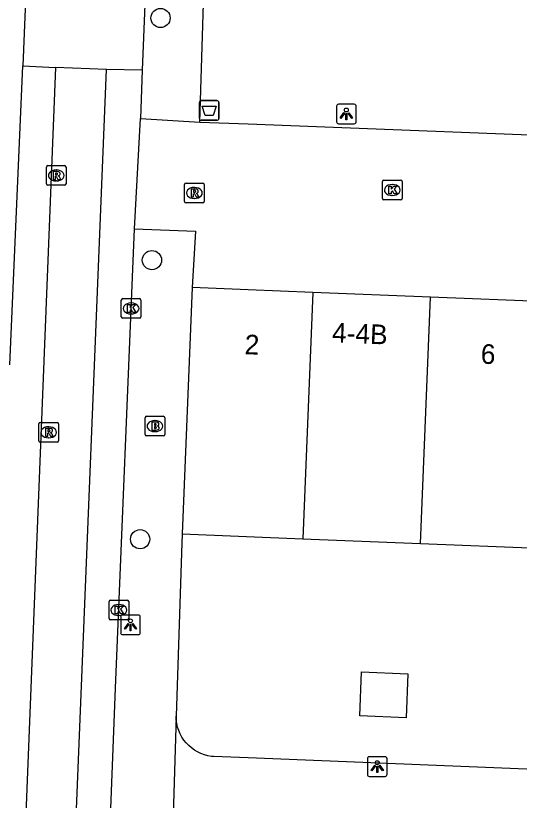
# Model space of a CAD drawing. Extents: x 160787 to 161428, y 386828 to 387483.
# Drawn here: x 160988.17 to 161013.79, y 387050.35 to 387090.27 of the extents above; entities that cross this region are included whole.
import ezdxf

# ---------------------------------------------------------------- set-up
doc = ezdxf.new("R2010")
doc.units = 0
for name, color, linetype in [('IMGEO_Afvalbak', 7, 'Continuous'), ('IMGEO_Boom', 7, 'Continuous'), ('IMGEO_Brandkraan', 7, 'Continuous'), ('IMGEO_Kolk', 7, 'Continuous'), ('IMGEO_Lichtpunt', 7, 'Continuous'), ('IMGEO_Pand', 7, 'Continuous'), ('IMGEO_Pand_nummerreeks', 7, 'Continuous'), ('IMGEO_Rijbaan_lokaal_gesloten', 7, 'Continuous'), ('IMGEO_Rijbaan_lokaal_open', 7, 'Continuous'), ('IMGEO_Rioolput', 7, 'Continuous'), ('IMGEO_Voetpad_open', 7, 'Continuous')]:
    doc.layers.add(name, color=color, linetype=linetype)

msp = doc.modelspace()

# ---------------------------------------------------------------- linework, layer by layer
at = {"layer": 'IMGEO_Afvalbak'}
for p, q in [((160997.617, 387085.95), (160998.407, 387085.95)), ((160998.407, 387085.95), (160997.617, 387085.95)), ((160997.517, 387085.05), (160997.517, 387085.85)), ((160997.517, 387085.85), (160997.517, 387085.05)), ((160998.507, 387085.85), (160998.507, 387085.05)), ((160998.507, 387085.05), (160998.507, 387085.85)), ((160998.407, 387084.95), (160997.617, 387084.95)), ((160997.617, 387084.95), (160998.407, 387084.95))]:
    msp.add_line(p, q, dxfattribs=at)
msp.add_lwpolyline([(160997.66, 387085.664), (160998.364, 387085.664), (160998.215, 387085.194), (160997.809, 387085.194), (160997.66, 387085.664)], dxfattribs=at)
for centre, start, end in [((160997.617, 387085.85), 90, 180), ((160997.617, 387085.85), 90, 180), ((160998.407, 387085.85), 0, 90), ((160998.407, 387085.85), 360, 90), ((160997.617, 387085.05), 180, 270), ((160997.617, 387085.05), 180, 270), ((160998.407, 387085.05), 270, 0), ((160998.407, 387085.05), 270, 0)]:
    msp.add_arc(centre, 0.1, start, end, dxfattribs=at)
at = {"layer": 'IMGEO_Boom'}
for centre in [(160995.542, 387090.155), (160995.105, 387077.836), (160994.503, 387063.636)]:
    msp.add_circle(centre, 0.489, dxfattribs=at)
at = {"layer": 'IMGEO_Brandkraan'}
for p, q in [((160994.757, 387068.964), (160994.757, 387069.816)), ((160994.832, 387069.89), (160995.684, 387069.89)), ((160995.245, 387069.67), (160995.27, 387069.67)), ((160995.758, 387069.816), (160995.758, 387068.964)), ((160995.684, 387068.89), (160994.832, 387068.89)), ((160995.268, 387069.11), (160995.243, 387069.11))]:
    msp.add_line(p, q, dxfattribs=at)
for points in [[(160994.757, 387068.964), (160994.757, 387069.816)], [(160994.832, 387069.89), (160995.684, 387069.89)], [(160995.105, 387069.59), (160995.105, 387069.19), (160995.318, 387069.19)], [(160995.336, 387069.59), (160995.105, 387069.59)], [(160995.758, 387069.816), (160995.758, 387068.964)], [(160995.284, 387069.509), (160995.23, 387069.509), (160995.23, 387069.433)], [(160995.23, 387069.433), (160995.283, 387069.433)], [(160995.292, 387069.357), (160995.23, 387069.357), (160995.23, 387069.276)], [(160995.23, 387069.276), (160995.292, 387069.276)], [(160995.684, 387068.89), (160994.832, 387068.89)]]:
    msp.add_lwpolyline(points, dxfattribs=at)
for centre, radius, start, end in [((160994.834, 387069.814), 0.0765, 91.552, 178.448), ((160994.834, 387069.814), 0.0765, 91.552, 178.448), ((160995.34, 387069.445), 0.145, 59.4692, 91.5367), ((160995.365, 387069.492), 0.0922, 285.5137, 58.1501), ((160995.682, 387069.814), 0.0765, 1.552, 88.448), ((160995.682, 387069.814), 0.0765, 1.552, 88.448), ((160995.285, 387069.471), 0.0379, 267.8285, 90.9355), ((160995.293, 387069.316), 0.0404, 269.8759, 90.5077), ((160995.324, 387069.441), 0.251, 268.6676, 293.5347), ((160995.37, 387069.3), 0.105, 301.3115, 78.989), ((160994.834, 387068.966), 0.0765, 181.552, 268.448), ((160994.834, 387068.966), 0.0765, 181.552, 268.448), ((160995.682, 387068.966), 0.0765, 271.552, 358.448), ((160995.682, 387068.966), 0.0765, 271.552, 358.448)]:
    msp.add_arc(centre, radius, start, end, dxfattribs=at)
for centre, major_axis, ratio, start_param, end_param in [((160995.244, 387069.39), (-0.387, 0.002), 0.722429, 4.712389, 7.853982), ((160995.269, 387069.39), (-0.39, 0.002), 0.717154, 1.570796, 4.712389)]:
    msp.add_ellipse(centre, major_axis=major_axis, ratio=ratio, start_param=start_param, end_param=end_param, dxfattribs=at)
at = {"layer": 'IMGEO_Kolk'}
for p, q in [((161006.83, 387080.978), (161006.83, 387081.83)), ((161006.905, 387081.904), (161007.757, 387081.904)), ((161007.318, 387081.684), (161007.343, 387081.684)), ((161007.831, 387081.83), (161007.831, 387080.978)), ((161007.341, 387081.124), (161007.316, 387081.124)), ((161007.757, 387080.904), (161006.905, 387080.904)), ((160993.545, 387074.951), (160993.545, 387075.803)), ((160993.62, 387075.877), (160994.472, 387075.877)), ((160994.033, 387075.657), (160994.058, 387075.657)), ((160994.546, 387075.803), (160994.546, 387074.951)), ((160994.472, 387074.877), (160993.62, 387074.877)), ((160994.056, 387075.097), (160994.031, 387075.097)), ((160992.921, 387059.609), (160992.921, 387060.461)), ((160992.996, 387060.535), (160993.848, 387060.535)), ((160993.922, 387060.461), (160993.922, 387059.609)), ((160993.409, 387060.315), (160993.434, 387060.315)), ((160993.432, 387059.755), (160993.407, 387059.755)), ((160993.848, 387059.535), (160992.996, 387059.535))]:
    msp.add_line(p, q, dxfattribs=at)
for points in [[(161006.83, 387080.978), (161006.83, 387081.83)], [(161006.905, 387081.904), (161007.757, 387081.904)], [(161007.151, 387081.604), (161007.274, 387081.604), (161007.274, 387081.453), (161007.404, 387081.604), (161007.568, 387081.604), (161007.422, 387081.453), (161007.575, 387081.204), (161007.423, 387081.204), (161007.338, 387081.368), (161007.274, 387081.301), (161007.274, 387081.204), (161007.151, 387081.204), (161007.151, 387081.604)], [(161007.831, 387081.83), (161007.831, 387080.978)], [(161007.757, 387080.904), (161006.905, 387080.904)], [(160993.545, 387074.951), (160993.545, 387075.803)], [(160993.62, 387075.877), (160994.472, 387075.877)], [(160993.866, 387075.577), (160993.989, 387075.577), (160993.989, 387075.426), (160994.119, 387075.577), (160994.283, 387075.577), (160994.137, 387075.426), (160994.29, 387075.177), (160994.138, 387075.177), (160994.053, 387075.341), (160993.989, 387075.274), (160993.989, 387075.177), (160993.866, 387075.177), (160993.866, 387075.577)], [(160994.546, 387075.803), (160994.546, 387074.951)], [(160994.472, 387074.877), (160993.62, 387074.877)], [(160992.921, 387059.609), (160992.921, 387060.461)], [(160992.996, 387060.535), (160993.848, 387060.535)], [(160993.922, 387060.461), (160993.922, 387059.609)], [(160993.242, 387060.235), (160993.365, 387060.235), (160993.365, 387060.084), (160993.495, 387060.235), (160993.659, 387060.235), (160993.513, 387060.084), (160993.666, 387059.835), (160993.514, 387059.835), (160993.429, 387059.999), (160993.365, 387059.932), (160993.365, 387059.835), (160993.242, 387059.835), (160993.242, 387060.235)], [(160993.848, 387059.535), (160992.996, 387059.535)]]:
    msp.add_lwpolyline(points, dxfattribs=at)
for centre, start, end in [((161006.907, 387081.828), 91.552, 178.448), ((161006.907, 387081.828), 91.552, 178.448), ((161007.755, 387081.828), 1.552, 88.448), ((161007.755, 387081.828), 1.552, 88.448), ((161006.907, 387080.98), 181.552, 268.448), ((161006.907, 387080.98), 181.552, 268.448), ((161007.755, 387080.98), 271.552, 358.448), ((161007.755, 387080.98), 271.552, 358.448), ((160993.622, 387075.801), 91.552, 178.448), ((160993.622, 387075.801), 91.552, 178.448), ((160994.47, 387075.801), 1.552, 88.448), ((160994.47, 387075.801), 1.552, 88.448), ((160993.622, 387074.953), 181.552, 268.448), ((160993.622, 387074.953), 181.552, 268.448), ((160994.47, 387074.953), 271.552, 358.448), ((160994.47, 387074.953), 271.552, 358.448), ((160992.998, 387060.459), 91.552, 178.448), ((160992.998, 387060.459), 91.552, 178.448), ((160993.846, 387060.459), 1.552, 88.448), ((160993.846, 387060.459), 1.552, 88.448), ((160992.998, 387059.611), 181.552, 268.448), ((160992.998, 387059.611), 181.552, 268.448), ((160993.846, 387059.611), 271.552, 358.448), ((160993.846, 387059.611), 271.552, 358.448)]:
    msp.add_arc(centre, 0.0765, start, end, dxfattribs=at)
for centre, major_axis, ratio, start_param, end_param in [((161007.317, 387081.404), (-0.387, 0.002), 0.722429, 4.712389, 7.853982), ((161007.342, 387081.404), (-0.39, 0.002), 0.717154, 1.570796, 4.712389), ((160994.032, 387075.377), (-0.387, 0.002), 0.722429, 4.712389, 7.853982), ((160994.057, 387075.377), (-0.39, 0.002), 0.717154, 1.570796, 4.712389), ((160993.408, 387060.035), (-0.387, 0.002), 0.722429, 4.712389, 7.853982), ((160993.433, 387060.035), (-0.39, 0.002), 0.717154, 1.570796, 4.712389)]:
    msp.add_ellipse(centre, major_axis=major_axis, ratio=ratio, start_param=start_param, end_param=end_param, dxfattribs=at)
at = {"layer": 'IMGEO_Lichtpunt'}
for p, q in [((161004.496, 387085.675), (161004.496, 387084.868)), ((161004.496, 387085.675), (161004.496, 387084.868)), ((161005.398, 387085.77), (161004.59, 387085.77)), ((161005.398, 387085.77), (161004.59, 387085.77)), ((161005.492, 387084.868), (161005.492, 387085.675)), ((161005.492, 387084.868), (161005.492, 387085.675)), ((161004.59, 387084.774), (161005.398, 387084.774)), ((161004.59, 387084.774), (161005.398, 387084.774)), ((160993.514, 387059.683), (160993.514, 387058.876)), ((160993.514, 387059.683), (160993.514, 387058.876)), ((160994.416, 387059.778), (160993.608, 387059.778)), ((160994.416, 387059.778), (160993.608, 387059.778)), ((160994.51, 387058.876), (160994.51, 387059.683)), ((160994.51, 387058.876), (160994.51, 387059.683)), ((160993.608, 387058.782), (160994.416, 387058.782)), ((160993.608, 387058.782), (160994.416, 387058.782)), ((161006.066, 387052.472), (161006.066, 387051.665)), ((161006.066, 387052.472), (161006.066, 387051.665)), ((161006.968, 387052.567), (161006.16, 387052.567)), ((161006.968, 387052.567), (161006.16, 387052.567)), ((161007.062, 387051.665), (161007.062, 387052.472)), ((161007.062, 387051.665), (161007.062, 387052.472)), ((161006.16, 387051.571), (161006.968, 387051.571)), ((161006.16, 387051.571), (161006.968, 387051.571))]:
    msp.add_line(p, q, dxfattribs=at)
for points in [[(161004.87, 387085.339), (161004.909, 387085.311), (161004.721, 387085.049), (161004.683, 387085.076), (161004.87, 387085.339)], [(161004.972, 387085.291), (161005.019, 387085.291), (161005.019, 387084.969), (161004.972, 387084.969), (161004.972, 387085.291)], [(161005.082, 387085.311), (161005.12, 387085.338), (161005.307, 387085.076), (161005.268, 387085.048), (161005.082, 387085.311)], [(160993.888, 387059.347), (160993.927, 387059.319), (160993.739, 387059.057), (160993.701, 387059.084), (160993.888, 387059.347)], [(160993.99, 387059.299), (160994.037, 387059.299), (160994.037, 387058.977), (160993.99, 387058.977), (160993.99, 387059.299)], [(160994.1, 387059.319), (160994.138, 387059.346), (160994.325, 387059.084), (160994.286, 387059.056), (160994.1, 387059.319)], [(161006.44, 387052.136), (161006.479, 387052.108), (161006.291, 387051.846), (161006.253, 387051.873), (161006.44, 387052.136)], [(161006.542, 387052.088), (161006.589, 387052.088), (161006.589, 387051.766), (161006.542, 387051.766), (161006.542, 387052.088)], [(161006.652, 387052.108), (161006.69, 387052.135), (161006.877, 387051.873), (161006.838, 387051.845), (161006.652, 387052.108)]]:
    msp.add_lwpolyline(points, dxfattribs=at)
for centre in [(161004.995, 387085.473), (160994.013, 387059.481), (161006.565, 387052.27)]:
    msp.add_circle(centre, 0.0994, dxfattribs=at)
for centre, start, end in [((161004.59, 387085.675), 90, 180), ((161004.59, 387085.675), 90, 180), ((161005.398, 387085.675), 0, 90), ((161005.398, 387085.675), 0, 90), ((161004.59, 387084.868), 180, 270), ((161004.59, 387084.868), 180, 270), ((161005.398, 387084.868), 270, 0), ((161005.398, 387084.868), 270, 360), ((160993.608, 387059.683), 90, 180), ((160993.608, 387059.683), 90, 180), ((160994.416, 387059.683), 0, 90), ((160994.416, 387059.683), 0, 90), ((160993.608, 387058.876), 180, 270), ((160993.608, 387058.876), 180, 270), ((160994.416, 387058.876), 270, 0), ((160994.416, 387058.876), 270, 360), ((161006.16, 387052.472), 90, 180), ((161006.16, 387052.472), 90, 180), ((161006.968, 387052.472), 0, 90), ((161006.968, 387052.472), 0, 90), ((161006.16, 387051.665), 180, 270), ((161006.16, 387051.665), 180, 270), ((161006.968, 387051.665), 270, 0), ((161006.968, 387051.665), 270, 360)]:
    msp.add_arc(centre, 0.0946, start, end, dxfattribs=at)
at = {"layer": 'IMGEO_Pand'}
for points in [[(160997.143, 387076.443), (160996.64, 387063.903)], [(161003.281, 387076.197), (161000, 387076.329), (160997.143, 387076.443)], [(161003.281, 387076.197), (161002.777, 387063.657)], [(161009.271, 387075.957), (161003.281, 387076.197)], [(161008.767, 387063.417), (161009.271, 387075.957)], [(161015.26, 387075.717), (161009.271, 387075.957)], [(160996.64, 387063.903), (161002.777, 387063.657)], [(161002.777, 387063.657), (161008.767, 387063.417)], [(161008.767, 387063.417), (161014.756, 387063.177)], [(161005.672, 387054.651), (161005.761, 387056.888), (161008.123, 387056.794), (161008.034, 387054.556), (161005.672, 387054.651)]]:
    msp.add_lwpolyline(points, dxfattribs=at)
at = {"layer": 'IMGEO_Rijbaan_lokaal_gesloten'}
for points in [[(160989.068, 387100.6), (160988.543, 387087.729)], [(160994.761, 387091.268), (160994.612, 387087.501)], [(160990.199, 387087.638), (160983.902, 386929.785), (160982.208, 386929.85)], [(160987.873, 387072.513), (160988.543, 387087.729)], [(160987.959, 386958.658), (160987.876, 386966.266), (160992.785, 387087.527)], [(160988.543, 387087.729), (160990.199, 387087.638)], [(160992.785, 387087.527), (160990.199, 387087.638)], [(160994.612, 387087.501), (160992.785, 387087.527)], [(160994.612, 387087.501), (160994.515, 387085.035)], [(160994.21, 387079.435), (160994.515, 387085.035)], [(160992.597, 387038.997), (160993.259, 387056.065), (160994.21, 387079.435)]]:
    msp.add_lwpolyline(points, dxfattribs=at)
at = {"layer": 'IMGEO_Rijbaan_lokaal_open'}
for points in [[(160994.515, 387085.035), (160997.543, 387084.863)], [(160997.543, 387084.863), (161000, 387084.767), (161019.96, 387083.995)], [(160994.21, 387079.435), (160997.327, 387079.303), (160997.143, 387076.443)]]:
    msp.add_lwpolyline(points, dxfattribs=at)
at = {"layer": 'IMGEO_Rioolput'}
for p, q in [((160989.736, 387081.718), (160989.736, 387082.57)), ((160989.811, 387082.644), (160990.663, 387082.644)), ((160990.224, 387082.424), (160990.249, 387082.424)), ((160990.737, 387082.57), (160990.737, 387081.718)), ((160990.663, 387081.644), (160989.811, 387081.644)), ((160990.247, 387081.864), (160990.222, 387081.864)), ((160996.763, 387080.827), (160996.763, 387081.679)), ((160996.838, 387081.753), (160997.69, 387081.753)), ((160997.251, 387081.533), (160997.276, 387081.533)), ((160997.764, 387081.679), (160997.764, 387080.827)), ((160997.69, 387080.753), (160996.838, 387080.753)), ((160997.274, 387080.973), (160997.249, 387080.973)), ((160989.426, 387069.576), (160990.278, 387069.576)), ((160989.351, 387068.65), (160989.351, 387069.502)), ((160989.839, 387069.356), (160989.864, 387069.356)), ((160990.352, 387069.502), (160990.352, 387068.65)), ((160989.862, 387068.796), (160989.837, 387068.796)), ((160990.278, 387068.576), (160989.426, 387068.576))]:
    msp.add_line(p, q, dxfattribs=at)
for points in [[(160989.736, 387081.718), (160989.736, 387082.57)], [(160989.811, 387082.644), (160990.663, 387082.644)], [(160990.325, 387082.342), (160990.073, 387082.344), (160990.073, 387081.944)], [(160990.737, 387082.57), (160990.737, 387081.718)], [(160990.073, 387081.944), (160990.197, 387081.944), (160990.197, 387082.106), (160990.208, 387082.106)], [(160990.251, 387082.263), (160990.197, 387082.263), (160990.197, 387082.182)], [(160990.197, 387082.182), (160990.249, 387082.182)], [(160990.255, 387082.077), (160990.326, 387081.944), (160990.466, 387081.944), (160990.401, 387082.07)], [(160990.663, 387081.644), (160989.811, 387081.644)], [(160996.763, 387080.827), (160996.763, 387081.679)], [(160996.838, 387081.753), (160997.69, 387081.753)], [(160997.764, 387081.679), (160997.764, 387080.827)], [(160997.352, 387081.451), (160997.1, 387081.453), (160997.1, 387081.053)], [(160997.1, 387081.053), (160997.224, 387081.053), (160997.224, 387081.215), (160997.235, 387081.215)], [(160997.278, 387081.372), (160997.224, 387081.372), (160997.224, 387081.291)], [(160997.224, 387081.291), (160997.276, 387081.291)], [(160997.282, 387081.186), (160997.353, 387081.053), (160997.493, 387081.053), (160997.428, 387081.179)], [(160997.69, 387080.753), (160996.838, 387080.753)], [(160989.426, 387069.576), (160990.278, 387069.576)], [(160989.351, 387068.65), (160989.351, 387069.502)], [(160989.94, 387069.274), (160989.688, 387069.276), (160989.688, 387068.876)], [(160989.866, 387069.195), (160989.812, 387069.195), (160989.812, 387069.114)], [(160990.352, 387069.502), (160990.352, 387068.65)], [(160989.688, 387068.876), (160989.812, 387068.876), (160989.812, 387069.038), (160989.823, 387069.038)], [(160989.812, 387069.114), (160989.864, 387069.114)], [(160989.87, 387069.009), (160989.941, 387068.876), (160990.081, 387068.876), (160990.016, 387069.002)], [(160990.278, 387068.576), (160989.426, 387068.576)]]:
    msp.add_lwpolyline(points, dxfattribs=at)
for centre, radius, start, end in [((160989.813, 387082.568), 0.0765, 91.552, 178.448), ((160989.813, 387082.568), 0.0765, 91.552, 178.448), ((160990.324, 387082.232), 0.109, 350.3612, 89.416), ((160990.661, 387082.568), 0.0765, 1.552, 88.448), ((160990.661, 387082.568), 0.0765, 1.552, 88.448), ((160990.207, 387082.053), 0.0533, 26.0293, 88.6989), ((160990.233, 387082.371), 0.19, 274.7715, 282.9687), ((160990.257, 387082.167), 0.0964, 77.0061, 93.1865), ((160990.271, 387082.224), 0.0378, 276.6634, 79.6772), ((160990.322, 387082.232), 0.112, 277.5842, 350.9817), ((160990.306, 387082.017), 0.108, 29.5134, 73.7905), ((160989.813, 387081.72), 0.0765, 181.552, 268.448), ((160989.813, 387081.72), 0.0765, 181.552, 268.448), ((160990.661, 387081.72), 0.0765, 271.552, 358.448), ((160990.661, 387081.72), 0.0765, 271.552, 358.448), ((160996.84, 387081.677), 0.0765, 91.552, 178.448), ((160996.84, 387081.677), 0.0765, 91.552, 178.448), ((160997.688, 387081.677), 0.0765, 1.552, 88.448), ((160997.688, 387081.677), 0.0765, 1.552, 88.448), ((160997.234, 387081.162), 0.0533, 26.0293, 88.6989), ((160997.26, 387081.48), 0.19, 274.7715, 282.9687), ((160997.284, 387081.276), 0.0964, 77.0061, 93.1865), ((160997.298, 387081.333), 0.0378, 276.6634, 79.6772), ((160997.351, 387081.341), 0.109, 350.3612, 89.416), ((160997.349, 387081.341), 0.112, 277.5842, 350.9817), ((160997.333, 387081.126), 0.108, 29.5134, 73.7905), ((160996.84, 387080.829), 0.0765, 181.552, 268.448), ((160996.84, 387080.829), 0.0765, 181.552, 268.448), ((160997.688, 387080.829), 0.0765, 271.552, 358.448), ((160997.688, 387080.829), 0.0765, 271.552, 358.448), ((160989.428, 387069.5), 0.0765, 91.552, 178.448), ((160989.428, 387069.5), 0.0765, 91.552, 178.448), ((160990.276, 387069.5), 0.0765, 1.552, 88.448), ((160990.276, 387069.5), 0.0765, 1.552, 88.448), ((160989.872, 387069.099), 0.0964, 77.0061, 93.1865), ((160989.886, 387069.156), 0.0378, 276.6634, 79.6772), ((160989.939, 387069.164), 0.109, 350.3612, 89.416), ((160989.937, 387069.164), 0.112, 277.5842, 350.9817), ((160989.822, 387068.985), 0.0533, 26.0293, 88.6989), ((160989.848, 387069.303), 0.19, 274.7715, 282.9687), ((160989.921, 387068.949), 0.108, 29.5134, 73.7905), ((160989.428, 387068.652), 0.0765, 181.552, 268.448), ((160989.428, 387068.652), 0.0765, 181.552, 268.448), ((160990.276, 387068.652), 0.0765, 271.552, 358.448), ((160990.276, 387068.652), 0.0765, 271.552, 358.448)]:
    msp.add_arc(centre, radius, start, end, dxfattribs=at)
for centre, major_axis, ratio, start_param, end_param in [((160990.223, 387082.144), (-0.387, 0.002), 0.722429, 4.712389, 7.853982), ((160990.248, 387082.144), (-0.39, 0.002), 0.717154, 1.570796, 4.712389), ((160997.25, 387081.253), (-0.387, 0.002), 0.722429, 4.712389, 7.853982), ((160997.275, 387081.253), (-0.39, 0.002), 0.717154, 1.570796, 4.712389), ((160989.838, 387069.076), (-0.387, 0.002), 0.722429, 4.712389, 7.853982), ((160989.863, 387069.076), (-0.39, 0.002), 0.717154, 1.570796, 4.712389)]:
    msp.add_ellipse(centre, major_axis=major_axis, ratio=ratio, start_param=start_param, end_param=end_param, dxfattribs=at)
at = {"layer": 'IMGEO_Voetpad_open'}
for points in [[(160997.543, 387084.863), (160997.748, 387091.453)], [(160996.64, 387063.903), (160996.602, 387062.949), (160996.331, 387054.633)], [(160996.331, 387054.633), (160996.129, 387047.914), (160996.149, 387047.763)], [(161036.645, 387051.029), (161000, 387052.509), (160998.235, 387052.578), (160998.132, 387052.589), (160997.949, 387052.622), (160997.77, 387052.671), (160997.596, 387052.736), (160997.428, 387052.816), (160997.269, 387052.911), (160997.118, 387053.019), (160996.978, 387053.141), (160996.849, 387053.274), (160996.733, 387053.419), (160996.63, 387053.574), (160996.541, 387053.737), (160996.467, 387053.907), (160996.409, 387054.083), (160996.367, 387054.264), (160996.341, 387054.448), (160996.331, 387054.633)]]:
    msp.add_lwpolyline(points, dxfattribs=at)

# ---------------------------------------------------------------- texts
at = {"layer": 'IMGEO_Pand_nummerreeks'}
for s, rotation, p in [('4-4B', 357.7082, (161004.251, 387073.656)), ('2', 357.7024, (160999.805, 387073.054)), ('6', 357.7024, (161011.816, 387072.572))]:
    msp.add_text(s, height=1, rotation=rotation, dxfattribs=at).set_placement(p)

doc.saveas('drawing.dxf')
